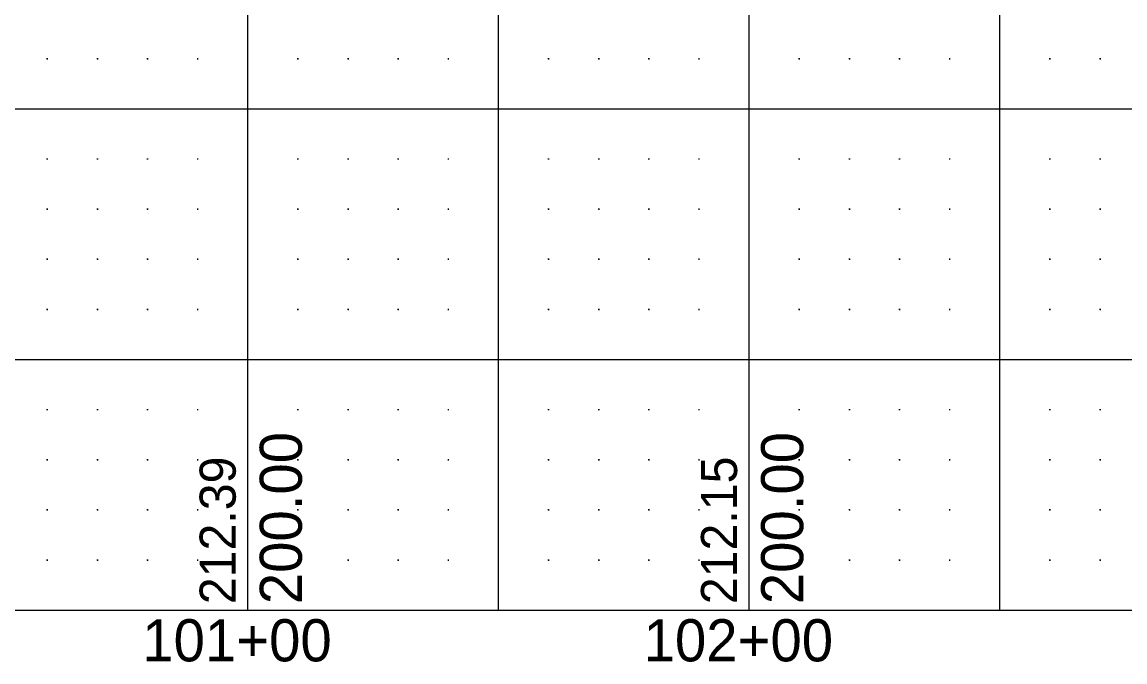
# Model space of a CAD drawing. Extents: x 471 to 2121, y 140 to 650.
# Drawn here: x 691 to 911, y 139.7 to 267.3 of the extents above; entities that cross this region are included whole.
import ezdxf

# ---------------------------------------------------------------- set-up
doc = ezdxf.new("R2010")
doc.units = 0
for name, color, linetype in [('DSN_DRFT_Border Grid', 7, 'Continuous'), ('DSN_RDWY_Prof Annotation', 7, 'Continuous'), ('EX_Profile Annotation', 7, 'Continuous')]:
    doc.layers.add(name, color=color, linetype=linetype)

msp = doc.modelspace()

# ---------------------------------------------------------------- linework, layer by layer
at = {"layer": 'DSN_DRFT_Border Grid'}
for p, q in [((736.06, 150), (736.06, 650)), ((736.06, 150), (736.06, 650)), ((786.06, 150), (786.06, 650)), ((786.06, 150), (786.06, 650)), ((836.06, 150), (836.06, 650)), ((836.06, 150), (836.06, 650)), ((886.06, 150), (886.06, 650)), ((886.06, 150), (886.06, 650)), ((696.18, 260), (695.94, 260)), ((696.18, 260), (695.94, 260)), ((696.06, 260.12), (696.06, 259.88)), ((696.06, 260.12), (696.06, 259.88)), ((706.18, 260), (705.94, 260)), ((706.18, 260), (705.94, 260)), ((706.06, 260.12), (706.06, 259.88)), ((706.06, 260.12), (706.06, 259.88)), ((716.18, 260), (715.94, 260)), ((716.18, 260), (715.94, 260)), ((716.06, 260.12), (716.06, 259.88)), ((716.06, 260.12), (716.06, 259.88)), ((726.18, 260), (725.94, 260)), ((726.18, 260), (725.94, 260)), ((726.06, 260.12), (726.06, 259.88)), ((726.06, 260.12), (726.06, 259.88)), ((746.18, 260), (745.94, 260)), ((746.18, 260), (745.94, 260)), ((746.06, 260.12), (746.06, 259.88)), ((746.06, 260.12), (746.06, 259.88)), ((756.18, 260), (755.94, 260)), ((756.18, 260), (755.94, 260)), ((756.06, 260.12), (756.06, 259.88)), ((756.06, 260.12), (756.06, 259.88)), ((766.18, 260), (765.94, 260)), ((766.18, 260), (765.94, 260)), ((766.06, 260.12), (766.06, 259.88)), ((766.06, 260.12), (766.06, 259.88)), ((776.18, 260), (775.94, 260)), ((776.18, 260), (775.94, 260)), ((776.06, 260.12), (776.06, 259.88)), ((776.06, 260.12), (776.06, 259.88)), ((796.18, 260), (795.94, 260)), ((796.18, 260), (795.94, 260)), ((796.06, 260.12), (796.06, 259.88)), ((796.06, 260.12), (796.06, 259.88)), ((806.18, 260), (805.94, 260)), ((806.18, 260), (805.94, 260)), ((806.06, 260.12), (806.06, 259.88)), ((806.06, 260.12), (806.06, 259.88)), ((816.18, 260), (815.94, 260)), ((816.18, 260), (815.94, 260)), ((816.06, 260.12), (816.06, 259.88)), ((816.06, 260.12), (816.06, 259.88)), ((826.18, 260), (825.94, 260)), ((826.18, 260), (825.94, 260)), ((826.06, 260.12), (826.06, 259.88)), ((826.06, 260.12), (826.06, 259.88)), ((846.18, 260), (845.94, 260)), ((846.18, 260), (845.94, 260)), ((846.06, 260.12), (846.06, 259.88)), ((846.06, 260.12), (846.06, 259.88)), ((856.18, 260), (855.94, 260)), ((856.18, 260), (855.94, 260)), ((856.06, 260.12), (856.06, 259.88)), ((856.06, 260.12), (856.06, 259.88)), ((866.18, 260), (865.94, 260)), ((866.18, 260), (865.94, 260)), ((866.06, 260.12), (866.06, 259.88)), ((866.06, 260.12), (866.06, 259.88)), ((876.18, 260), (875.94, 260)), ((876.18, 260), (875.94, 260)), ((876.06, 260.12), (876.06, 259.88)), ((876.06, 260.12), (876.06, 259.88)), ((896.18, 260), (895.94, 260)), ((896.18, 260), (895.94, 260)), ((896.06, 260.12), (896.06, 259.88)), ((896.06, 260.12), (896.06, 259.88)), ((906.18, 260), (905.94, 260)), ((906.18, 260), (905.94, 260)), ((906.06, 260.12), (906.06, 259.88)), ((906.06, 260.12), (906.06, 259.88)), ((521.06, 250), (2071.06, 250)), ((521.06, 250), (2071.06, 250)), ((696.18, 240), (695.94, 240)), ((696.18, 240), (695.94, 240)), ((696.06, 240.12), (696.06, 239.88)), ((696.06, 240.12), (696.06, 239.88)), ((706.18, 240), (705.94, 240)), ((706.18, 240), (705.94, 240)), ((706.06, 240.12), (706.06, 239.88)), ((706.06, 240.12), (706.06, 239.88)), ((716.18, 240), (715.94, 240)), ((716.18, 240), (715.94, 240)), ((716.06, 240.12), (716.06, 239.88)), ((716.06, 240.12), (716.06, 239.88)), ((726.18, 240), (725.94, 240)), ((726.18, 240), (725.94, 240)), ((726.06, 240.12), (726.06, 239.88)), ((726.06, 240.12), (726.06, 239.88)), ((746.18, 240), (745.94, 240)), ((746.18, 240), (745.94, 240)), ((746.06, 240.12), (746.06, 239.88)), ((746.06, 240.12), (746.06, 239.88)), ((756.18, 240), (755.94, 240)), ((756.18, 240), (755.94, 240)), ((756.06, 240.12), (756.06, 239.88)), ((756.06, 240.12), (756.06, 239.88)), ((766.18, 240), (765.94, 240)), ((766.18, 240), (765.94, 240)), ((766.06, 240.12), (766.06, 239.88)), ((766.06, 240.12), (766.06, 239.88)), ((776.18, 240), (775.94, 240)), ((776.18, 240), (775.94, 240)), ((776.06, 240.12), (776.06, 239.88)), ((776.06, 240.12), (776.06, 239.88)), ((796.18, 240), (795.94, 240)), ((796.18, 240), (795.94, 240)), ((796.06, 240.12), (796.06, 239.88)), ((796.06, 240.12), (796.06, 239.88)), ((806.18, 240), (805.94, 240)), ((806.18, 240), (805.94, 240)), ((806.06, 240.12), (806.06, 239.88)), ((806.06, 240.12), (806.06, 239.88)), ((816.18, 240), (815.94, 240)), ((816.18, 240), (815.94, 240)), ((816.06, 240.12), (816.06, 239.88)), ((816.06, 240.12), (816.06, 239.88)), ((826.18, 240), (825.94, 240)), ((826.18, 240), (825.94, 240)), ((826.06, 240.12), (826.06, 239.88)), ((826.06, 240.12), (826.06, 239.88)), ((846.18, 240), (845.94, 240)), ((846.18, 240), (845.94, 240)), ((846.06, 240.12), (846.06, 239.88)), ((846.06, 240.12), (846.06, 239.88)), ((856.18, 240), (855.94, 240)), ((856.18, 240), (855.94, 240)), ((856.06, 240.12), (856.06, 239.88)), ((856.06, 240.12), (856.06, 239.88)), ((866.18, 240), (865.94, 240)), ((866.18, 240), (865.94, 240)), ((866.06, 240.12), (866.06, 239.88)), ((866.06, 240.12), (866.06, 239.88)), ((876.18, 240), (875.94, 240)), ((876.18, 240), (875.94, 240)), ((876.06, 240.12), (876.06, 239.88)), ((876.06, 240.12), (876.06, 239.88)), ((896.18, 240), (895.94, 240)), ((896.18, 240), (895.94, 240)), ((896.06, 240.12), (896.06, 239.88)), ((896.06, 240.12), (896.06, 239.88)), ((906.18, 240), (905.94, 240)), ((906.18, 240), (905.94, 240)), ((906.06, 240.12), (906.06, 239.88)), ((906.06, 240.12), (906.06, 239.88)), ((696.18, 230), (695.94, 230)), ((696.18, 230), (695.94, 230)), ((696.06, 230.12), (696.06, 229.88)), ((696.06, 230.12), (696.06, 229.88)), ((706.18, 230), (705.94, 230)), ((706.18, 230), (705.94, 230)), ((706.06, 230.12), (706.06, 229.88)), ((706.06, 230.12), (706.06, 229.88)), ((716.18, 230), (715.94, 230)), ((716.18, 230), (715.94, 230)), ((716.06, 230.12), (716.06, 229.88)), ((716.06, 230.12), (716.06, 229.88)), ((726.18, 230), (725.94, 230)), ((726.18, 230), (725.94, 230)), ((726.06, 230.12), (726.06, 229.88)), ((726.06, 230.12), (726.06, 229.88)), ((746.18, 230), (745.94, 230)), ((746.18, 230), (745.94, 230)), ((746.06, 230.12), (746.06, 229.88)), ((746.06, 230.12), (746.06, 229.88)), ((756.18, 230), (755.94, 230)), ((756.18, 230), (755.94, 230)), ((756.06, 230.12), (756.06, 229.88)), ((756.06, 230.12), (756.06, 229.88)), ((766.18, 230), (765.94, 230)), ((766.18, 230), (765.94, 230)), ((766.06, 230.12), (766.06, 229.88)), ((766.06, 230.12), (766.06, 229.88)), ((776.18, 230), (775.94, 230)), ((776.18, 230), (775.94, 230)), ((776.06, 230.12), (776.06, 229.88)), ((776.06, 230.12), (776.06, 229.88)), ((796.18, 230), (795.94, 230)), ((796.18, 230), (795.94, 230)), ((796.06, 230.12), (796.06, 229.88)), ((796.06, 230.12), (796.06, 229.88)), ((806.18, 230), (805.94, 230)), ((806.18, 230), (805.94, 230)), ((806.06, 230.12), (806.06, 229.88)), ((806.06, 230.12), (806.06, 229.88)), ((816.18, 230), (815.94, 230)), ((816.18, 230), (815.94, 230)), ((816.06, 230.12), (816.06, 229.88)), ((816.06, 230.12), (816.06, 229.88)), ((826.18, 230), (825.94, 230)), ((826.18, 230), (825.94, 230)), ((826.06, 230.12), (826.06, 229.88)), ((826.06, 230.12), (826.06, 229.88)), ((846.18, 230), (845.94, 230)), ((846.18, 230), (845.94, 230)), ((846.06, 230.12), (846.06, 229.88)), ((846.06, 230.12), (846.06, 229.88)), ((856.18, 230), (855.94, 230)), ((856.18, 230), (855.94, 230)), ((856.06, 230.12), (856.06, 229.88)), ((856.06, 230.12), (856.06, 229.88)), ((866.18, 230), (865.94, 230)), ((866.18, 230), (865.94, 230)), ((866.06, 230.12), (866.06, 229.88)), ((866.06, 230.12), (866.06, 229.88)), ((876.18, 230), (875.94, 230)), ((876.18, 230), (875.94, 230)), ((876.06, 230.12), (876.06, 229.88)), ((876.06, 230.12), (876.06, 229.88)), ((896.18, 230), (895.94, 230)), ((896.18, 230), (895.94, 230)), ((896.06, 230.12), (896.06, 229.88)), ((896.06, 230.12), (896.06, 229.88)), ((906.18, 230), (905.94, 230)), ((906.18, 230), (905.94, 230)), ((906.06, 230.12), (906.06, 229.88)), ((906.06, 230.12), (906.06, 229.88)), ((696.18, 220), (695.94, 220)), ((696.18, 220), (695.94, 220)), ((696.06, 220.12), (696.06, 219.88)), ((696.06, 220.12), (696.06, 219.88)), ((706.18, 220), (705.94, 220)), ((706.18, 220), (705.94, 220)), ((706.06, 220.12), (706.06, 219.88)), ((706.06, 220.12), (706.06, 219.88)), ((716.18, 220), (715.94, 220)), ((716.18, 220), (715.94, 220)), ((716.06, 220.12), (716.06, 219.88)), ((716.06, 220.12), (716.06, 219.88)), ((726.18, 220), (725.94, 220)), ((726.18, 220), (725.94, 220)), ((726.06, 220.12), (726.06, 219.88)), ((726.06, 220.12), (726.06, 219.88)), ((746.18, 220), (745.94, 220)), ((746.18, 220), (745.94, 220)), ((746.06, 220.12), (746.06, 219.88)), ((746.06, 220.12), (746.06, 219.88)), ((756.18, 220), (755.94, 220)), ((756.18, 220), (755.94, 220)), ((756.06, 220.12), (756.06, 219.88)), ((756.06, 220.12), (756.06, 219.88)), ((766.18, 220), (765.94, 220)), ((766.18, 220), (765.94, 220)), ((766.06, 220.12), (766.06, 219.88)), ((766.06, 220.12), (766.06, 219.88)), ((776.18, 220), (775.94, 220)), ((776.18, 220), (775.94, 220)), ((776.06, 220.12), (776.06, 219.88)), ((776.06, 220.12), (776.06, 219.88)), ((796.18, 220), (795.94, 220)), ((796.18, 220), (795.94, 220)), ((796.06, 220.12), (796.06, 219.88)), ((796.06, 220.12), (796.06, 219.88)), ((806.18, 220), (805.94, 220)), ((806.18, 220), (805.94, 220)), ((806.06, 220.12), (806.06, 219.88)), ((806.06, 220.12), (806.06, 219.88)), ((816.18, 220), (815.94, 220)), ((816.18, 220), (815.94, 220)), ((816.06, 220.12), (816.06, 219.88)), ((816.06, 220.12), (816.06, 219.88)), ((826.18, 220), (825.94, 220)), ((826.18, 220), (825.94, 220)), ((826.06, 220.12), (826.06, 219.88)), ((826.06, 220.12), (826.06, 219.88)), ((846.18, 220), (845.94, 220)), ((846.18, 220), (845.94, 220)), ((846.06, 220.12), (846.06, 219.88)), ((846.06, 220.12), (846.06, 219.88)), ((856.18, 220), (855.94, 220)), ((856.18, 220), (855.94, 220)), ((856.06, 220.12), (856.06, 219.88)), ((856.06, 220.12), (856.06, 219.88)), ((866.18, 220), (865.94, 220)), ((866.18, 220), (865.94, 220)), ((866.06, 220.12), (866.06, 219.88)), ((866.06, 220.12), (866.06, 219.88)), ((876.18, 220), (875.94, 220)), ((876.18, 220), (875.94, 220)), ((876.06, 220.12), (876.06, 219.88)), ((876.06, 220.12), (876.06, 219.88)), ((896.18, 220), (895.94, 220)), ((896.18, 220), (895.94, 220)), ((896.06, 220.12), (896.06, 219.88)), ((896.06, 220.12), (896.06, 219.88)), ((906.18, 220), (905.94, 220)), ((906.18, 220), (905.94, 220)), ((906.06, 220.12), (906.06, 219.88)), ((906.06, 220.12), (906.06, 219.88)), ((696.18, 210), (695.94, 210)), ((696.18, 210), (695.94, 210)), ((696.06, 210.12), (696.06, 209.88)), ((696.06, 210.12), (696.06, 209.88)), ((706.18, 210), (705.94, 210)), ((706.18, 210), (705.94, 210)), ((706.06, 210.12), (706.06, 209.88)), ((706.06, 210.12), (706.06, 209.88)), ((716.18, 210), (715.94, 210)), ((716.18, 210), (715.94, 210)), ((716.06, 210.12), (716.06, 209.88)), ((716.06, 210.12), (716.06, 209.88)), ((726.18, 210), (725.94, 210)), ((726.18, 210), (725.94, 210)), ((726.06, 210.12), (726.06, 209.88)), ((726.06, 210.12), (726.06, 209.88)), ((746.18, 210), (745.94, 210)), ((746.18, 210), (745.94, 210)), ((746.06, 210.12), (746.06, 209.88)), ((746.06, 210.12), (746.06, 209.88)), ((756.18, 210), (755.94, 210)), ((756.18, 210), (755.94, 210)), ((756.06, 210.12), (756.06, 209.88)), ((756.06, 210.12), (756.06, 209.88)), ((766.18, 210), (765.94, 210)), ((766.18, 210), (765.94, 210)), ((766.06, 210.12), (766.06, 209.88)), ((766.06, 210.12), (766.06, 209.88)), ((776.18, 210), (775.94, 210)), ((776.18, 210), (775.94, 210)), ((776.06, 210.12), (776.06, 209.88)), ((776.06, 210.12), (776.06, 209.88)), ((796.18, 210), (795.94, 210)), ((796.18, 210), (795.94, 210)), ((796.06, 210.12), (796.06, 209.88)), ((796.06, 210.12), (796.06, 209.88)), ((806.18, 210), (805.94, 210)), ((806.18, 210), (805.94, 210)), ((806.06, 210.12), (806.06, 209.88)), ((806.06, 210.12), (806.06, 209.88)), ((816.18, 210), (815.94, 210)), ((816.18, 210), (815.94, 210)), ((816.06, 210.12), (816.06, 209.88)), ((816.06, 210.12), (816.06, 209.88)), ((826.18, 210), (825.94, 210)), ((826.18, 210), (825.94, 210)), ((826.06, 210.12), (826.06, 209.88)), ((826.06, 210.12), (826.06, 209.88)), ((846.18, 210), (845.94, 210)), ((846.18, 210), (845.94, 210)), ((846.06, 210.12), (846.06, 209.88)), ((846.06, 210.12), (846.06, 209.88)), ((856.18, 210), (855.94, 210)), ((856.18, 210), (855.94, 210)), ((856.06, 210.12), (856.06, 209.88)), ((856.06, 210.12), (856.06, 209.88)), ((866.18, 210), (865.94, 210)), ((866.18, 210), (865.94, 210)), ((866.06, 210.12), (866.06, 209.88)), ((866.06, 210.12), (866.06, 209.88)), ((876.18, 210), (875.94, 210)), ((876.18, 210), (875.94, 210)), ((876.06, 210.12), (876.06, 209.88)), ((876.06, 210.12), (876.06, 209.88)), ((896.18, 210), (895.94, 210)), ((896.18, 210), (895.94, 210)), ((896.06, 210.12), (896.06, 209.88)), ((896.06, 210.12), (896.06, 209.88)), ((906.18, 210), (905.94, 210)), ((906.18, 210), (905.94, 210)), ((906.06, 210.12), (906.06, 209.88)), ((906.06, 210.12), (906.06, 209.88)), ((521.06, 200), (2071.06, 200)), ((521.06, 200), (2071.06, 200)), ((696.18, 190), (695.94, 190)), ((696.18, 190), (695.94, 190)), ((696.06, 190.12), (696.06, 189.88)), ((696.06, 190.12), (696.06, 189.88)), ((706.18, 190), (705.94, 190)), ((706.18, 190), (705.94, 190)), ((706.06, 190.12), (706.06, 189.88)), ((706.06, 190.12), (706.06, 189.88)), ((716.18, 190), (715.94, 190)), ((716.18, 190), (715.94, 190)), ((716.06, 190.12), (716.06, 189.88)), ((716.06, 190.12), (716.06, 189.88)), ((726.18, 190), (725.94, 190)), ((726.18, 190), (725.94, 190)), ((726.06, 190.12), (726.06, 189.88)), ((726.06, 190.12), (726.06, 189.88)), ((746.18, 190), (745.94, 190)), ((746.18, 190), (745.94, 190)), ((746.06, 190.12), (746.06, 189.88)), ((746.06, 190.12), (746.06, 189.88)), ((756.18, 190), (755.94, 190)), ((756.18, 190), (755.94, 190)), ((756.06, 190.12), (756.06, 189.88)), ((756.06, 190.12), (756.06, 189.88)), ((766.18, 190), (765.94, 190)), ((766.18, 190), (765.94, 190)), ((766.06, 190.12), (766.06, 189.88)), ((766.06, 190.12), (766.06, 189.88)), ((776.18, 190), (775.94, 190)), ((776.18, 190), (775.94, 190)), ((776.06, 190.12), (776.06, 189.88)), ((776.06, 190.12), (776.06, 189.88)), ((796.18, 190), (795.94, 190)), ((796.18, 190), (795.94, 190)), ((796.06, 190.12), (796.06, 189.88)), ((796.06, 190.12), (796.06, 189.88)), ((806.18, 190), (805.94, 190)), ((806.18, 190), (805.94, 190)), ((806.06, 190.12), (806.06, 189.88)), ((806.06, 190.12), (806.06, 189.88)), ((816.18, 190), (815.94, 190)), ((816.18, 190), (815.94, 190)), ((816.06, 190.12), (816.06, 189.88)), ((816.06, 190.12), (816.06, 189.88)), ((826.18, 190), (825.94, 190)), ((826.18, 190), (825.94, 190)), ((826.06, 190.12), (826.06, 189.88)), ((826.06, 190.12), (826.06, 189.88)), ((846.18, 190), (845.94, 190)), ((846.18, 190), (845.94, 190)), ((846.06, 190.12), (846.06, 189.88)), ((846.06, 190.12), (846.06, 189.88)), ((856.18, 190), (855.94, 190)), ((856.18, 190), (855.94, 190)), ((856.06, 190.12), (856.06, 189.88)), ((856.06, 190.12), (856.06, 189.88)), ((866.18, 190), (865.94, 190)), ((866.18, 190), (865.94, 190)), ((866.06, 190.12), (866.06, 189.88)), ((866.06, 190.12), (866.06, 189.88)), ((876.18, 190), (875.94, 190)), ((876.18, 190), (875.94, 190)), ((876.06, 190.12), (876.06, 189.88)), ((876.06, 190.12), (876.06, 189.88)), ((896.18, 190), (895.94, 190)), ((896.18, 190), (895.94, 190)), ((896.06, 190.12), (896.06, 189.88)), ((896.06, 190.12), (896.06, 189.88)), ((906.18, 190), (905.94, 190)), ((906.18, 190), (905.94, 190)), ((906.06, 190.12), (906.06, 189.88)), ((906.06, 190.12), (906.06, 189.88)), ((696.18, 180), (695.94, 180)), ((696.18, 180), (695.94, 180)), ((696.06, 180.12), (696.06, 179.88)), ((696.06, 180.12), (696.06, 179.88)), ((706.18, 180), (705.94, 180)), ((706.18, 180), (705.94, 180)), ((706.06, 180.12), (706.06, 179.88)), ((706.06, 180.12), (706.06, 179.88)), ((716.18, 180), (715.94, 180)), ((716.18, 180), (715.94, 180)), ((716.06, 180.12), (716.06, 179.88)), ((716.06, 180.12), (716.06, 179.88)), ((726.18, 180), (725.94, 180)), ((726.18, 180), (725.94, 180)), ((726.06, 180.12), (726.06, 179.88)), ((726.06, 180.12), (726.06, 179.88)), ((746.18, 180), (745.94, 180)), ((746.18, 180), (745.94, 180)), ((746.06, 180.12), (746.06, 179.88)), ((746.06, 180.12), (746.06, 179.88)), ((756.18, 180), (755.94, 180)), ((756.18, 180), (755.94, 180)), ((756.06, 180.12), (756.06, 179.88)), ((756.06, 180.12), (756.06, 179.88)), ((766.18, 180), (765.94, 180)), ((766.18, 180), (765.94, 180)), ((766.06, 180.12), (766.06, 179.88)), ((766.06, 180.12), (766.06, 179.88)), ((776.18, 180), (775.94, 180)), ((776.18, 180), (775.94, 180)), ((776.06, 180.12), (776.06, 179.88)), ((776.06, 180.12), (776.06, 179.88)), ((796.18, 180), (795.94, 180)), ((796.18, 180), (795.94, 180)), ((796.06, 180.12), (796.06, 179.88)), ((796.06, 180.12), (796.06, 179.88)), ((806.18, 180), (805.94, 180)), ((806.18, 180), (805.94, 180)), ((806.06, 180.12), (806.06, 179.88)), ((806.06, 180.12), (806.06, 179.88)), ((816.18, 180), (815.94, 180)), ((816.18, 180), (815.94, 180)), ((816.06, 180.12), (816.06, 179.88)), ((816.06, 180.12), (816.06, 179.88)), ((826.18, 180), (825.94, 180)), ((826.18, 180), (825.94, 180)), ((826.06, 180.12), (826.06, 179.88)), ((826.06, 180.12), (826.06, 179.88)), ((846.18, 180), (845.94, 180)), ((846.18, 180), (845.94, 180)), ((846.06, 180.12), (846.06, 179.88)), ((846.06, 180.12), (846.06, 179.88)), ((856.18, 180), (855.94, 180)), ((856.18, 180), (855.94, 180)), ((856.06, 180.12), (856.06, 179.88)), ((856.06, 180.12), (856.06, 179.88)), ((866.18, 180), (865.94, 180)), ((866.18, 180), (865.94, 180)), ((866.06, 180.12), (866.06, 179.88)), ((866.06, 180.12), (866.06, 179.88)), ((876.18, 180), (875.94, 180)), ((876.18, 180), (875.94, 180)), ((876.06, 180.12), (876.06, 179.88)), ((876.06, 180.12), (876.06, 179.88)), ((896.18, 180), (895.94, 180)), ((896.18, 180), (895.94, 180)), ((896.06, 180.12), (896.06, 179.88)), ((896.06, 180.12), (896.06, 179.88)), ((906.18, 180), (905.94, 180)), ((906.18, 180), (905.94, 180)), ((906.06, 180.12), (906.06, 179.88)), ((906.06, 180.12), (906.06, 179.88)), ((696.18, 170), (695.94, 170)), ((696.18, 170), (695.94, 170)), ((696.06, 170.12), (696.06, 169.88)), ((696.06, 170.12), (696.06, 169.88)), ((706.18, 170), (705.94, 170)), ((706.18, 170), (705.94, 170)), ((706.06, 170.12), (706.06, 169.88)), ((706.06, 170.12), (706.06, 169.88)), ((716.18, 170), (715.94, 170)), ((716.18, 170), (715.94, 170)), ((716.06, 170.12), (716.06, 169.88)), ((716.06, 170.12), (716.06, 169.88)), ((726.18, 170), (725.94, 170)), ((726.18, 170), (725.94, 170)), ((726.06, 170.12), (726.06, 169.88)), ((726.06, 170.12), (726.06, 169.88)), ((746.18, 170), (745.94, 170)), ((746.18, 170), (745.94, 170)), ((746.06, 170.12), (746.06, 169.88)), ((746.06, 170.12), (746.06, 169.88)), ((756.18, 170), (755.94, 170)), ((756.18, 170), (755.94, 170)), ((756.06, 170.12), (756.06, 169.88)), ((756.06, 170.12), (756.06, 169.88)), ((766.18, 170), (765.94, 170)), ((766.18, 170), (765.94, 170)), ((766.06, 170.12), (766.06, 169.88)), ((766.06, 170.12), (766.06, 169.88)), ((776.18, 170), (775.94, 170)), ((776.18, 170), (775.94, 170)), ((776.06, 170.12), (776.06, 169.88)), ((776.06, 170.12), (776.06, 169.88)), ((796.18, 170), (795.94, 170)), ((796.18, 170), (795.94, 170)), ((796.06, 170.12), (796.06, 169.88)), ((796.06, 170.12), (796.06, 169.88)), ((806.18, 170), (805.94, 170)), ((806.18, 170), (805.94, 170)), ((806.06, 170.12), (806.06, 169.88)), ((806.06, 170.12), (806.06, 169.88)), ((816.18, 170), (815.94, 170)), ((816.18, 170), (815.94, 170)), ((816.06, 170.12), (816.06, 169.88)), ((816.06, 170.12), (816.06, 169.88)), ((826.18, 170), (825.94, 170)), ((826.18, 170), (825.94, 170)), ((826.06, 170.12), (826.06, 169.88)), ((826.06, 170.12), (826.06, 169.88)), ((846.18, 170), (845.94, 170)), ((846.18, 170), (845.94, 170)), ((846.06, 170.12), (846.06, 169.88)), ((846.06, 170.12), (846.06, 169.88)), ((856.18, 170), (855.94, 170)), ((856.18, 170), (855.94, 170)), ((856.06, 170.12), (856.06, 169.88)), ((856.06, 170.12), (856.06, 169.88)), ((866.18, 170), (865.94, 170)), ((866.18, 170), (865.94, 170)), ((866.06, 170.12), (866.06, 169.88)), ((866.06, 170.12), (866.06, 169.88)), ((876.18, 170), (875.94, 170)), ((876.18, 170), (875.94, 170)), ((876.06, 170.12), (876.06, 169.88)), ((876.06, 170.12), (876.06, 169.88)), ((896.18, 170), (895.94, 170)), ((896.18, 170), (895.94, 170)), ((896.06, 170.12), (896.06, 169.88)), ((896.06, 170.12), (896.06, 169.88)), ((906.18, 170), (905.94, 170)), ((906.18, 170), (905.94, 170)), ((906.06, 170.12), (906.06, 169.88)), ((906.06, 170.12), (906.06, 169.88)), ((696.18, 160), (695.94, 160)), ((696.18, 160), (695.94, 160)), ((696.06, 160.12), (696.06, 159.88)), ((696.06, 160.12), (696.06, 159.88)), ((706.18, 160), (705.94, 160)), ((706.18, 160), (705.94, 160)), ((706.06, 160.12), (706.06, 159.88)), ((706.06, 160.12), (706.06, 159.88)), ((716.18, 160), (715.94, 160)), ((716.18, 160), (715.94, 160)), ((716.06, 160.12), (716.06, 159.88)), ((716.06, 160.12), (716.06, 159.88)), ((726.18, 160), (725.94, 160)), ((726.18, 160), (725.94, 160)), ((726.06, 160.12), (726.06, 159.88)), ((726.06, 160.12), (726.06, 159.88)), ((746.18, 160), (745.94, 160)), ((746.18, 160), (745.94, 160)), ((746.06, 160.12), (746.06, 159.88)), ((746.06, 160.12), (746.06, 159.88)), ((756.18, 160), (755.94, 160)), ((756.18, 160), (755.94, 160)), ((756.06, 160.12), (756.06, 159.88)), ((756.06, 160.12), (756.06, 159.88)), ((766.18, 160), (765.94, 160)), ((766.18, 160), (765.94, 160)), ((766.06, 160.12), (766.06, 159.88)), ((766.06, 160.12), (766.06, 159.88)), ((776.18, 160), (775.94, 160)), ((776.18, 160), (775.94, 160)), ((776.06, 160.12), (776.06, 159.88)), ((776.06, 160.12), (776.06, 159.88)), ((796.18, 160), (795.94, 160)), ((796.18, 160), (795.94, 160)), ((796.06, 160.12), (796.06, 159.88)), ((796.06, 160.12), (796.06, 159.88)), ((806.18, 160), (805.94, 160)), ((806.18, 160), (805.94, 160)), ((806.06, 160.12), (806.06, 159.88)), ((806.06, 160.12), (806.06, 159.88)), ((816.18, 160), (815.94, 160)), ((816.18, 160), (815.94, 160)), ((816.06, 160.12), (816.06, 159.88)), ((816.06, 160.12), (816.06, 159.88)), ((826.18, 160), (825.94, 160)), ((826.18, 160), (825.94, 160)), ((826.06, 160.12), (826.06, 159.88)), ((826.06, 160.12), (826.06, 159.88)), ((846.18, 160), (845.94, 160)), ((846.18, 160), (845.94, 160)), ((846.06, 160.12), (846.06, 159.88)), ((846.06, 160.12), (846.06, 159.88)), ((856.18, 160), (855.94, 160)), ((856.18, 160), (855.94, 160)), ((856.06, 160.12), (856.06, 159.88)), ((856.06, 160.12), (856.06, 159.88)), ((866.18, 160), (865.94, 160)), ((866.18, 160), (865.94, 160)), ((866.06, 160.12), (866.06, 159.88)), ((866.06, 160.12), (866.06, 159.88)), ((876.18, 160), (875.94, 160)), ((876.18, 160), (875.94, 160)), ((876.06, 160.12), (876.06, 159.88)), ((876.06, 160.12), (876.06, 159.88)), ((896.18, 160), (895.94, 160)), ((896.18, 160), (895.94, 160)), ((896.06, 160.12), (896.06, 159.88)), ((896.06, 160.12), (896.06, 159.88)), ((906.18, 160), (905.94, 160)), ((906.18, 160), (905.94, 160)), ((906.06, 160.12), (906.06, 159.88)), ((906.06, 160.12), (906.06, 159.88)), ((521.06, 150), (2071.06, 150)), ((521.06, 150), (2071.06, 150))]:
    msp.add_line(p, q, dxfattribs=at)

# ---------------------------------------------------------------- texts
at = {"layer": 'DSN_RDWY_Prof Annotation'}
for p in [(746.86, 151.2), (846.86, 151.2)]:
    msp.add_text('200.00', height=8.4, rotation=90, dxfattribs=at).set_placement(p)
for s, p in [('101+00', (715.02, 139.8)), ('101+00', (715.02, 139.8)), ('102+00', (815.02, 139.8)), ('102+00', (815.02, 139.8))]:
    msp.add_text(s, height=8.4, dxfattribs=at).set_placement(p)
at = {"layer": 'EX_Profile Annotation'}
for s, p in [('212.39', (733.66, 151.2)), ('212.15', (833.66, 151.2))]:
    msp.add_text(s, height=7.2, rotation=90, dxfattribs=at).set_placement(p)

doc.saveas('drawing.dxf')
